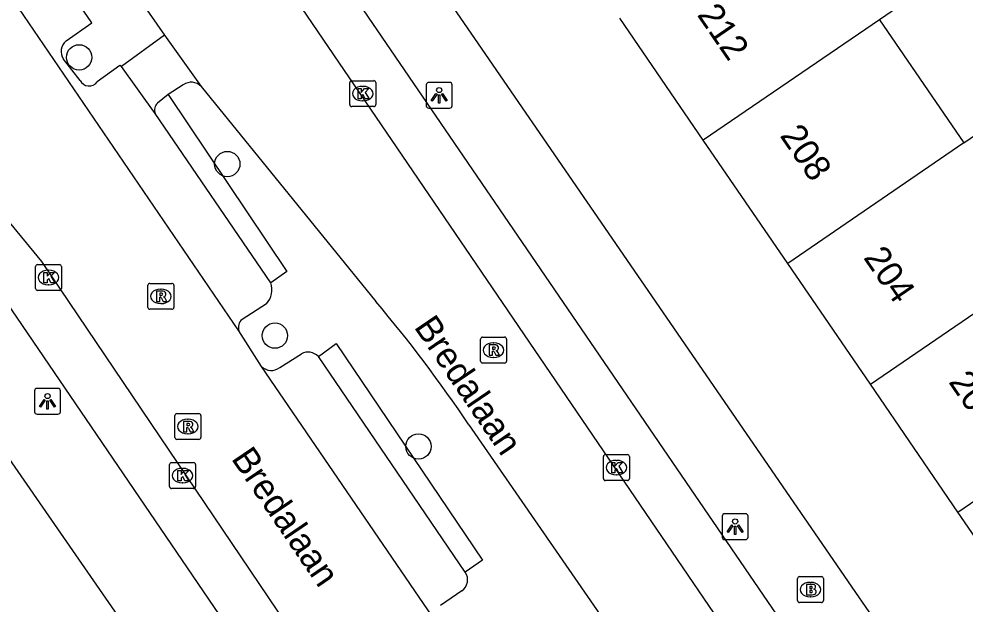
# Model space of a CAD drawing. Extents: x 158087 to 159494, y 382905 to 383981.
# Drawn here: x 158364.19 to 158400.72, y 383423.73 to 383446.33 of the extents above; entities that cross this region are included whole.
import ezdxf

# ---------------------------------------------------------------- set-up
doc = ezdxf.new("R2010")
doc.units = 0
for name, color, linetype in [('IMGEO_Boom', 7, 'Continuous'), ('IMGEO_Brandkraan', 7, 'Continuous'), ('IMGEO_Kolk', 7, 'Continuous'), ('IMGEO_Lichtpunt', 7, 'Continuous'), ('IMGEO_Openbare_ruimte_label', 7, 'Continuous'), ('IMGEO_Pand', 7, 'Continuous'), ('IMGEO_Pand_nummerreeks', 7, 'Continuous'), ('IMGEO_Parkeervlak_open', 7, 'Continuous'), ('IMGEO_Rijbaan_lokaal_gesloten', 7, 'Continuous'), ('IMGEO_Rioolput', 7, 'Continuous'), ('IMGEO_Voetpad_open', 7, 'Continuous')]:
    doc.layers.add(name, color=color, linetype=linetype)

msp = doc.modelspace()

# ---------------------------------------------------------------- linework, layer by layer
at = {"layer": 'IMGEO_Boom'}
for centre in [(158366.511, 383444.84), (158372.233, 383440.721), (158374.071, 383434.094), (158379.615, 383429.812)]:
    msp.add_circle(centre, 0.489, dxfattribs=at)
at = {"layer": 'IMGEO_Brandkraan'}
for p, q in [((158394.253, 383423.86), (158394.253, 383424.712)), ((158394.328, 383424.786), (158395.18, 383424.786)), ((158394.741, 383424.566), (158394.766, 383424.566)), ((158395.254, 383424.712), (158395.254, 383423.86)), ((158394.764, 383424.006), (158394.739, 383424.006)), ((158395.18, 383423.786), (158394.328, 383423.786))]:
    msp.add_line(p, q, dxfattribs=at)
for points in [[(158394.253, 383423.86), (158394.253, 383424.712)], [(158394.328, 383424.786), (158395.18, 383424.786)], [(158395.254, 383424.712), (158395.254, 383423.86)], [(158394.601, 383424.486), (158394.601, 383424.086), (158394.814, 383424.086)], [(158394.832, 383424.486), (158394.601, 383424.486)], [(158394.78, 383424.405), (158394.726, 383424.405), (158394.726, 383424.329)], [(158394.726, 383424.329), (158394.779, 383424.329)], [(158394.788, 383424.253), (158394.726, 383424.253), (158394.726, 383424.172)], [(158394.726, 383424.172), (158394.788, 383424.172)], [(158395.18, 383423.786), (158394.328, 383423.786)]]:
    msp.add_lwpolyline(points, dxfattribs=at)
for centre, radius, start, end in [((158394.33, 383424.71), 0.0765, 91.552, 178.448), ((158394.33, 383424.71), 0.0765, 91.552, 178.448), ((158395.178, 383424.71), 0.0765, 1.552, 88.448), ((158395.178, 383424.71), 0.0765, 1.552, 88.448), ((158394.781, 383424.367), 0.0379, 267.8285, 90.9355), ((158394.789, 383424.212), 0.0404, 269.8759, 90.5077), ((158394.836, 383424.341), 0.145, 59.4692, 91.5367), ((158394.861, 383424.388), 0.0922, 285.5137, 58.1501), ((158394.866, 383424.196), 0.105, 301.3115, 78.989), ((158394.33, 383423.862), 0.0765, 181.552, 268.448), ((158394.33, 383423.862), 0.0765, 181.552, 268.448), ((158394.82, 383424.337), 0.251, 268.6676, 293.5347), ((158395.178, 383423.862), 0.0765, 271.552, 358.448), ((158395.178, 383423.862), 0.0765, 271.552, 358.448)]:
    msp.add_arc(centre, radius, start, end, dxfattribs=at)
for centre, major_axis, ratio, start_param, end_param in [((158394.74, 383424.286), (-0.387, 0.002), 0.722429, 4.712389, 7.853982), ((158394.765, 383424.286), (-0.39, 0.002), 0.717154, 1.570796, 4.712389)]:
    msp.add_ellipse(centre, major_axis=major_axis, ratio=ratio, start_param=start_param, end_param=end_param, dxfattribs=at)
at = {"layer": 'IMGEO_Kolk'}
for p, q in [((158377.036, 383443.94), (158377.888, 383443.94)), ((158376.961, 383443.014), (158376.961, 383443.866)), ((158377.449, 383443.72), (158377.474, 383443.72)), ((158377.962, 383443.866), (158377.962, 383443.014)), ((158377.472, 383443.16), (158377.447, 383443.16)), ((158377.888, 383442.94), (158377.036, 383442.94)), ((158364.826, 383435.912), (158364.826, 383436.764)), ((158364.901, 383436.838), (158365.753, 383436.838)), ((158365.314, 383436.618), (158365.339, 383436.618)), ((158365.827, 383436.764), (158365.827, 383435.912)), ((158365.337, 383436.058), (158365.312, 383436.058)), ((158365.753, 383435.838), (158364.901, 383435.838)), ((158386.757, 383428.571), (158386.757, 383429.423)), ((158386.832, 383429.497), (158387.684, 383429.497)), ((158387.245, 383429.277), (158387.27, 383429.277)), ((158387.758, 383429.423), (158387.758, 383428.571)), ((158370.005, 383428.262), (158370.005, 383429.114)), ((158370.08, 383429.188), (158370.932, 383429.188)), ((158370.493, 383428.968), (158370.518, 383428.968)), ((158371.006, 383429.114), (158371.006, 383428.262)), ((158387.268, 383428.717), (158387.243, 383428.717)), ((158370.932, 383428.188), (158370.08, 383428.188)), ((158370.516, 383428.408), (158370.491, 383428.408)), ((158387.684, 383428.497), (158386.832, 383428.497))]:
    msp.add_line(p, q, dxfattribs=at)
for points in [[(158377.036, 383443.94), (158377.888, 383443.94)], [(158376.961, 383443.014), (158376.961, 383443.866)], [(158377.282, 383443.64), (158377.405, 383443.64), (158377.405, 383443.489), (158377.535, 383443.64), (158377.699, 383443.64), (158377.553, 383443.489), (158377.706, 383443.24), (158377.554, 383443.24), (158377.469, 383443.404), (158377.405, 383443.337), (158377.405, 383443.24), (158377.282, 383443.24), (158377.282, 383443.64)], [(158377.962, 383443.866), (158377.962, 383443.014)], [(158377.888, 383442.94), (158377.036, 383442.94)], [(158364.826, 383435.912), (158364.826, 383436.764)], [(158364.901, 383436.838), (158365.753, 383436.838)], [(158365.827, 383436.764), (158365.827, 383435.912)], [(158365.147, 383436.538), (158365.27, 383436.538), (158365.27, 383436.387), (158365.4, 383436.538), (158365.564, 383436.538), (158365.418, 383436.387), (158365.571, 383436.138), (158365.419, 383436.138), (158365.334, 383436.302), (158365.27, 383436.235), (158365.27, 383436.138), (158365.147, 383436.138), (158365.147, 383436.538)], [(158365.753, 383435.838), (158364.901, 383435.838)], [(158386.757, 383428.571), (158386.757, 383429.423)], [(158386.832, 383429.497), (158387.684, 383429.497)], [(158387.758, 383429.423), (158387.758, 383428.571)], [(158370.005, 383428.262), (158370.005, 383429.114)], [(158370.08, 383429.188), (158370.932, 383429.188)], [(158371.006, 383429.114), (158371.006, 383428.262)], [(158387.078, 383429.197), (158387.201, 383429.197), (158387.201, 383429.046), (158387.331, 383429.197), (158387.495, 383429.197), (158387.349, 383429.046), (158387.502, 383428.797), (158387.35, 383428.797), (158387.265, 383428.961), (158387.201, 383428.894), (158387.201, 383428.797), (158387.078, 383428.797), (158387.078, 383429.197)], [(158370.326, 383428.888), (158370.449, 383428.888), (158370.449, 383428.737), (158370.579, 383428.888), (158370.743, 383428.888), (158370.597, 383428.737), (158370.75, 383428.488), (158370.598, 383428.488), (158370.513, 383428.652), (158370.449, 383428.585), (158370.449, 383428.488), (158370.326, 383428.488), (158370.326, 383428.888)], [(158370.932, 383428.188), (158370.08, 383428.188)], [(158387.684, 383428.497), (158386.832, 383428.497)]]:
    msp.add_lwpolyline(points, dxfattribs=at)
for centre, start, end in [((158377.038, 383443.864), 91.552, 178.448), ((158377.038, 383443.864), 91.552, 178.448), ((158377.886, 383443.864), 1.552, 88.448), ((158377.886, 383443.864), 1.552, 88.448), ((158377.038, 383443.016), 181.552, 268.448), ((158377.038, 383443.016), 181.552, 268.448), ((158377.886, 383443.016), 271.552, 358.448), ((158377.886, 383443.016), 271.552, 358.448), ((158364.903, 383436.762), 91.552, 178.448), ((158364.903, 383436.762), 91.552, 178.448), ((158365.751, 383436.762), 1.552, 88.448), ((158365.751, 383436.762), 1.552, 88.448), ((158364.903, 383435.914), 181.552, 268.448), ((158364.903, 383435.914), 181.552, 268.448), ((158365.751, 383435.914), 271.552, 358.448), ((158365.751, 383435.914), 271.552, 358.448), ((158386.834, 383429.421), 91.552, 178.448), ((158386.834, 383429.421), 91.552, 178.448), ((158387.682, 383429.421), 1.552, 88.448), ((158387.682, 383429.421), 1.552, 88.448), ((158370.082, 383429.112), 91.552, 178.448), ((158370.082, 383429.112), 91.552, 178.448), ((158370.93, 383429.112), 1.552, 88.448), ((158370.93, 383429.112), 1.552, 88.448), ((158386.834, 383428.573), 181.552, 268.448), ((158386.834, 383428.573), 181.552, 268.448), ((158387.682, 383428.573), 271.552, 358.448), ((158387.682, 383428.573), 271.552, 358.448), ((158370.082, 383428.264), 181.552, 268.448), ((158370.082, 383428.264), 181.552, 268.448), ((158370.93, 383428.264), 271.552, 358.448), ((158370.93, 383428.264), 271.552, 358.448)]:
    msp.add_arc(centre, 0.0765, start, end, dxfattribs=at)
for centre, major_axis, ratio, start_param, end_param in [((158377.448, 383443.44), (-0.387, 0.002), 0.722429, 4.712389, 7.853982), ((158377.473, 383443.44), (-0.39, 0.002), 0.717154, 1.570796, 4.712389), ((158365.313, 383436.338), (-0.387, 0.002), 0.722429, 4.712389, 7.853982), ((158365.338, 383436.338), (-0.39, 0.002), 0.717154, 1.570796, 4.712389), ((158387.244, 383428.997), (-0.387, 0.002), 0.722429, 4.712389, 7.853982), ((158387.269, 383428.997), (-0.39, 0.002), 0.717154, 1.570796, 4.712389), ((158370.492, 383428.688), (-0.387, 0.002), 0.722429, 4.712389, 7.853982), ((158370.517, 383428.688), (-0.39, 0.002), 0.717154, 1.570796, 4.712389)]:
    msp.add_ellipse(centre, major_axis=major_axis, ratio=ratio, start_param=start_param, end_param=end_param, dxfattribs=at)
at = {"layer": 'IMGEO_Lichtpunt'}
for p, q in [((158379.917, 383443.779), (158379.917, 383442.972)), ((158379.917, 383443.779), (158379.917, 383442.972)), ((158380.819, 383443.874), (158380.011, 383443.874)), ((158380.819, 383443.874), (158380.011, 383443.874)), ((158380.913, 383442.972), (158380.913, 383443.779)), ((158380.913, 383442.972), (158380.913, 383443.779)), ((158380.011, 383442.878), (158380.819, 383442.878)), ((158380.011, 383442.878), (158380.819, 383442.878)), ((158364.791, 383431.962), (158364.791, 383431.155)), ((158364.791, 383431.962), (158364.791, 383431.155)), ((158365.693, 383432.057), (158364.885, 383432.057)), ((158365.693, 383432.057), (158364.885, 383432.057)), ((158365.787, 383431.155), (158365.787, 383431.962)), ((158365.787, 383431.155), (158365.787, 383431.962)), ((158364.885, 383431.061), (158365.693, 383431.061)), ((158364.885, 383431.061), (158365.693, 383431.061)), ((158391.344, 383427.118), (158391.344, 383426.311)), ((158391.344, 383427.118), (158391.344, 383426.311)), ((158392.246, 383427.213), (158391.438, 383427.213)), ((158392.246, 383427.213), (158391.438, 383427.213)), ((158392.34, 383426.311), (158392.34, 383427.118)), ((158392.34, 383426.311), (158392.34, 383427.118)), ((158391.438, 383426.217), (158392.246, 383426.217)), ((158391.438, 383426.217), (158392.246, 383426.217))]:
    msp.add_line(p, q, dxfattribs=at)
for points in [[(158380.291, 383443.443), (158380.33, 383443.415), (158380.142, 383443.153), (158380.104, 383443.18), (158380.291, 383443.443)], [(158380.393, 383443.395), (158380.44, 383443.395), (158380.44, 383443.073), (158380.393, 383443.073), (158380.393, 383443.395)], [(158380.503, 383443.415), (158380.541, 383443.442), (158380.728, 383443.18), (158380.689, 383443.152), (158380.503, 383443.415)], [(158365.165, 383431.626), (158365.204, 383431.598), (158365.016, 383431.336), (158364.978, 383431.363), (158365.165, 383431.626)], [(158365.267, 383431.578), (158365.314, 383431.578), (158365.314, 383431.256), (158365.267, 383431.256), (158365.267, 383431.578)], [(158365.377, 383431.598), (158365.415, 383431.625), (158365.602, 383431.363), (158365.563, 383431.335), (158365.377, 383431.598)], [(158391.718, 383426.782), (158391.757, 383426.754), (158391.569, 383426.492), (158391.531, 383426.519), (158391.718, 383426.782)], [(158391.82, 383426.734), (158391.867, 383426.734), (158391.867, 383426.412), (158391.82, 383426.412), (158391.82, 383426.734)], [(158391.93, 383426.754), (158391.968, 383426.781), (158392.155, 383426.519), (158392.116, 383426.491), (158391.93, 383426.754)]]:
    msp.add_lwpolyline(points, dxfattribs=at)
for centre in [(158380.416, 383443.577), (158365.29, 383431.76), (158391.843, 383426.916)]:
    msp.add_circle(centre, 0.0994, dxfattribs=at)
for centre, start, end in [((158380.011, 383443.779), 90, 180), ((158380.011, 383443.779), 90, 180), ((158380.819, 383443.779), 0, 90), ((158380.819, 383443.779), 0, 90), ((158380.011, 383442.972), 180, 270), ((158380.011, 383442.972), 180, 270), ((158380.819, 383442.972), 270, 0), ((158380.819, 383442.972), 270, 360), ((158364.885, 383431.962), 90, 180), ((158364.885, 383431.962), 90, 180), ((158365.693, 383431.962), 0, 90), ((158365.693, 383431.962), 0, 90), ((158364.885, 383431.155), 180, 270), ((158364.885, 383431.155), 180, 270), ((158365.693, 383431.155), 270, 0), ((158365.693, 383431.155), 270, 360), ((158391.438, 383427.118), 90, 180), ((158391.438, 383427.118), 90, 180), ((158392.246, 383427.118), 0, 90), ((158392.246, 383427.118), 0, 90), ((158391.438, 383426.311), 180, 270), ((158391.438, 383426.311), 180, 270), ((158392.246, 383426.311), 270, 0), ((158392.246, 383426.311), 270, 360)]:
    msp.add_arc(centre, 0.0946, start, end, dxfattribs=at)
at = {"layer": 'IMGEO_Pand'}
for points in [[(158394.185, 383451.012), (158397.142, 383453.036), (158400.371, 383448.32), (158397.415, 383446.295)], [(158390.614, 383441.639), (158387.385, 383446.355)], [(158397.415, 383446.295), (158390.614, 383441.639)], [(158397.415, 383446.295), (158400.675, 383441.535)], [(158400.675, 383441.535), (158403.402, 383443.402), (158406.597, 383438.736), (158403.87, 383436.869)], [(158393.874, 383436.878), (158390.614, 383441.639)], [(158400.675, 383441.535), (158393.874, 383436.878)], [(158397.069, 383432.213), (158393.874, 383436.878)], [(158397.069, 383432.213), (158403.87, 383436.869)], [(158400.449, 383427.277), (158397.069, 383432.213)], [(158400.449, 383427.277), (158407.25, 383431.934)], [(158403.707, 383422.52), (158400.449, 383427.277)]]:
    msp.add_lwpolyline(points, dxfattribs=at)
at = {"layer": 'IMGEO_Parkeervlak_open'}
for points in [[(158366.006, 383445.478), (158366.999, 383446.169), (158364.864, 383449.3)], [(158366.548, 383443.952), (158365.907, 383444.775)], [(158368.143, 383444.491), (158368.078, 383444.527), (158367.205, 383443.893)], [(158373.742, 383435.327), (158372.804, 383434.723)], [(158374.256, 383432.859), (158375.091, 383433.391)], [(158381.287, 383424.239), (158380.468, 383423.667)]]:
    msp.add_lwpolyline(points, dxfattribs=at)
for centre, radius, start, end in [((158366.337, 383445.073), 0.523, 129.2497, 214.7183), ((158366.894, 383444.117), 0.383, 205.443, 324.294), ((158373.172, 383435.869), 0.787, 316.4561, 19.3641), ((158373.054, 383434.416), 0.396, 129.1521, 200.4248), ((158375.351, 383432.904), 0.552, 43.7847, 118.0823), ((158373.93, 383433.286), 0.537, 225.4842, 307.3428), ((158381.003, 383424.662), 0.51, 303.8617, 34.7246)]:
    msp.add_arc(centre, radius, start, end, dxfattribs=at)
at = {"layer": 'IMGEO_Rijbaan_lokaal_gesloten'}
for points in [[(158363.428, 383454.856), (158369.808, 383445.696)], [(158372.683, 383434.278), (158360.881, 383451.568)], [(158398.608, 383412.252), (158373.072, 383449.747)], [(158369.808, 383445.696), (158371.223, 383443.713)], [(158371.223, 383443.713), (158377.969, 383435.412)], [(158363.028, 383439.413), (158365.052, 383436.959), (158376.95, 383419.335)], [(158373.554, 383432.903), (158372.683, 383434.278)], [(158380.338, 383422.981), (158373.554, 383432.903)], [(158381.565, 383430.647), (158386.868, 383422.971)]]:
    msp.add_lwpolyline(points, dxfattribs=at)
msp.add_arc((158336.279, 383400.211), 54.563, 33.9049, 40.1766, dxfattribs=at)
at = {"layer": 'IMGEO_Rioolput'}
for p, q in [((158369.166, 383435.185), (158369.166, 383436.037)), ((158369.241, 383436.111), (158370.093, 383436.111)), ((158369.654, 383435.891), (158369.679, 383435.891)), ((158370.167, 383436.037), (158370.167, 383435.185)), ((158369.677, 383435.331), (158369.652, 383435.331)), ((158370.093, 383435.111), (158369.241, 383435.111)), ((158382.088, 383434.034), (158382.94, 383434.034)), ((158382.013, 383433.108), (158382.013, 383433.96)), ((158382.501, 383433.814), (158382.526, 383433.814)), ((158383.014, 383433.96), (158383.014, 383433.108)), ((158382.94, 383433.034), (158382.088, 383433.034)), ((158382.524, 383433.254), (158382.499, 383433.254)), ((158370.209, 383430.157), (158370.209, 383431.009)), ((158370.284, 383431.083), (158371.136, 383431.083)), ((158370.697, 383430.863), (158370.722, 383430.863)), ((158371.21, 383431.009), (158371.21, 383430.157)), ((158371.136, 383430.083), (158370.284, 383430.083)), ((158370.72, 383430.303), (158370.695, 383430.303))]:
    msp.add_line(p, q, dxfattribs=at)
for points in [[(158369.166, 383435.185), (158369.166, 383436.037)], [(158369.241, 383436.111), (158370.093, 383436.111)], [(158370.167, 383436.037), (158370.167, 383435.185)], [(158369.755, 383435.809), (158369.503, 383435.811), (158369.503, 383435.411)], [(158369.503, 383435.411), (158369.627, 383435.411), (158369.627, 383435.573), (158369.638, 383435.573)], [(158369.681, 383435.73), (158369.627, 383435.73), (158369.627, 383435.649)], [(158369.627, 383435.649), (158369.679, 383435.649)], [(158369.685, 383435.544), (158369.756, 383435.411), (158369.896, 383435.411), (158369.831, 383435.537)], [(158370.093, 383435.111), (158369.241, 383435.111)], [(158382.088, 383434.034), (158382.94, 383434.034)], [(158382.013, 383433.108), (158382.013, 383433.96)], [(158382.602, 383433.732), (158382.35, 383433.734), (158382.35, 383433.334)], [(158382.528, 383433.653), (158382.474, 383433.653), (158382.474, 383433.572)], [(158383.014, 383433.96), (158383.014, 383433.108)], [(158382.35, 383433.334), (158382.474, 383433.334), (158382.474, 383433.496), (158382.485, 383433.496)], [(158382.474, 383433.572), (158382.526, 383433.572)], [(158382.532, 383433.467), (158382.603, 383433.334), (158382.743, 383433.334), (158382.678, 383433.46)], [(158382.94, 383433.034), (158382.088, 383433.034)], [(158370.209, 383430.157), (158370.209, 383431.009)], [(158370.284, 383431.083), (158371.136, 383431.083)], [(158370.798, 383430.781), (158370.546, 383430.783), (158370.546, 383430.383)], [(158371.21, 383431.009), (158371.21, 383430.157)], [(158370.546, 383430.383), (158370.67, 383430.383), (158370.67, 383430.545), (158370.681, 383430.545)], [(158370.724, 383430.702), (158370.67, 383430.702), (158370.67, 383430.621)], [(158370.67, 383430.621), (158370.722, 383430.621)], [(158370.728, 383430.516), (158370.799, 383430.383), (158370.939, 383430.383), (158370.874, 383430.509)], [(158371.136, 383430.083), (158370.284, 383430.083)]]:
    msp.add_lwpolyline(points, dxfattribs=at)
for centre, radius, start, end in [((158369.243, 383436.035), 0.0765, 91.552, 178.448), ((158369.243, 383436.035), 0.0765, 91.552, 178.448), ((158370.091, 383436.035), 0.0765, 1.552, 88.448), ((158370.091, 383436.035), 0.0765, 1.552, 88.448), ((158369.637, 383435.52), 0.0533, 26.0293, 88.6989), ((158369.663, 383435.838), 0.19, 274.7715, 282.9687), ((158369.687, 383435.634), 0.0964, 77.0061, 93.1865), ((158369.701, 383435.691), 0.0378, 276.6634, 79.6772), ((158369.754, 383435.699), 0.109, 350.3612, 89.416), ((158369.752, 383435.699), 0.112, 277.5842, 350.9817), ((158369.736, 383435.484), 0.108, 29.5134, 73.7905), ((158369.243, 383435.187), 0.0765, 181.552, 268.448), ((158369.243, 383435.187), 0.0765, 181.552, 268.448), ((158370.091, 383435.187), 0.0765, 271.552, 358.448), ((158370.091, 383435.187), 0.0765, 271.552, 358.448), ((158382.09, 383433.958), 0.0765, 91.552, 178.448), ((158382.09, 383433.958), 0.0765, 91.552, 178.448), ((158382.938, 383433.958), 0.0765, 1.552, 88.448), ((158382.938, 383433.958), 0.0765, 1.552, 88.448), ((158382.534, 383433.557), 0.0964, 77.0061, 93.1865), ((158382.548, 383433.614), 0.0378, 276.6634, 79.6772), ((158382.601, 383433.622), 0.109, 350.3612, 89.416), ((158382.484, 383433.443), 0.0533, 26.0293, 88.6989), ((158382.51, 383433.761), 0.19, 274.7715, 282.9687), ((158382.599, 383433.622), 0.112, 277.5842, 350.9817), ((158382.583, 383433.407), 0.108, 29.5134, 73.7905), ((158382.09, 383433.11), 0.0765, 181.552, 268.448), ((158382.09, 383433.11), 0.0765, 181.552, 268.448), ((158382.938, 383433.11), 0.0765, 271.552, 358.448), ((158382.938, 383433.11), 0.0765, 271.552, 358.448), ((158370.286, 383431.007), 0.0765, 91.552, 178.448), ((158370.286, 383431.007), 0.0765, 91.552, 178.448), ((158370.797, 383430.671), 0.109, 350.3612, 89.416), ((158371.134, 383431.007), 0.0765, 1.552, 88.448), ((158371.134, 383431.007), 0.0765, 1.552, 88.448), ((158370.68, 383430.492), 0.0533, 26.0293, 88.6989), ((158370.706, 383430.81), 0.19, 274.7715, 282.9687), ((158370.73, 383430.606), 0.0964, 77.0061, 93.1865), ((158370.744, 383430.663), 0.0378, 276.6634, 79.6772), ((158370.795, 383430.671), 0.112, 277.5842, 350.9817), ((158370.779, 383430.456), 0.108, 29.5134, 73.7905), ((158370.286, 383430.159), 0.0765, 181.552, 268.448), ((158370.286, 383430.159), 0.0765, 181.552, 268.448), ((158371.134, 383430.159), 0.0765, 271.552, 358.448), ((158371.134, 383430.159), 0.0765, 271.552, 358.448)]:
    msp.add_arc(centre, radius, start, end, dxfattribs=at)
for centre, major_axis, ratio, start_param, end_param in [((158369.653, 383435.611), (-0.387, 0.002), 0.722429, 4.712389, 7.853982), ((158369.678, 383435.611), (-0.39, 0.002), 0.717154, 1.570796, 4.712389), ((158382.5, 383433.534), (-0.387, 0.002), 0.722429, 4.712389, 7.853982), ((158382.525, 383433.534), (-0.39, 0.002), 0.717154, 1.570796, 4.712389), ((158370.696, 383430.583), (-0.387, 0.002), 0.722429, 4.712389, 7.853982), ((158370.721, 383430.583), (-0.39, 0.002), 0.717154, 1.570796, 4.712389)]:
    msp.add_ellipse(centre, major_axis=major_axis, ratio=ratio, start_param=start_param, end_param=end_param, dxfattribs=at)
at = {"layer": 'IMGEO_Voetpad_open'}
for points in [[(158403.057, 383414.649), (158377.599, 383451.689), (158376.413, 383453.622), (158373.221, 383460.141)], [(158374.251, 383448.734), (158376.264, 383448.16), (158376.78, 383447.712), (158398.711, 383415.61), (158398.844, 383414.853), (158398.477, 383413.3)], [(158369.808, 383445.696), (158368.143, 383444.491)], [(158349.641, 383444.76), (158358.306, 383437.257), (158379.659, 383406.433), (158373.579, 383402.215)], [(158369.445, 383442.671), (158368.143, 383444.491)], [(158370.53, 383443.777), (158369.946, 383443.401)], [(158369.946, 383443.401), (158369.538, 383443.074)], [(158369.946, 383443.401), (158374.53, 383436.574), (158373.914, 383436.13)], [(158373.914, 383436.13), (158369.445, 383442.671)], [(158375.832, 383417.584), (158363.498, 383435.698), (158363.26, 383436.427), (158363.437, 383438.109)], [(158375.749, 383433.286), (158376.439, 383433.794), (158382.09, 383425.428), (158381.422, 383424.953)], [(158381.422, 383424.953), (158375.749, 383433.286)]]:
    msp.add_lwpolyline(points, dxfattribs=at)
for centre, radius, start, end in [((158370.841, 383443.364), 0.517, 42.4349, 127.0123), ((158369.79, 383442.804), 0.37, 133.0247, 200.986)]:
    msp.add_arc(centre, radius, start, end, dxfattribs=at)

# ---------------------------------------------------------------- texts
at = {"layer": 'IMGEO_Openbare_ruimte_label'}
for p in [(158379.419, 383434.427), (158372.362, 383429.346)]:
    msp.add_text('Bredalaan', height=1, rotation=304.246, dxfattribs=at).set_placement(p)
at = {"layer": 'IMGEO_Pand_nummerreeks'}
for s, rotation, p in [('212', 304.4, (158390.35, 383446.484)), ('208', 304.4039, (158393.547, 383441.817)), ('204', 304.4039, (158396.772, 383437.107)), ('200', 304.4039, (158400.062, 383432.304))]:
    msp.add_text(s, height=1, rotation=rotation, dxfattribs=at).set_placement(p)

doc.saveas('drawing.dxf')
